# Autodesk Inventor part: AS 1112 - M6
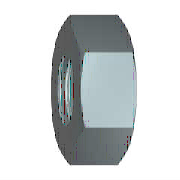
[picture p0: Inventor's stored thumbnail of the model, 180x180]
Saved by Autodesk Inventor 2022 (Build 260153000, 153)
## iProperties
Created: 2021-02
Part Number: AS 1112 - M6
Material: Acciaio, Dolce
Description: Dadi esagonali metrici ISO, inclusi dadi sottili, dadi con intaglio e dadi a corona
Document SubType Name: Modeling
Standard: AS 1112
Designer: admin
Standards Organization: AS
Language: it-IT
Size Designation: M6
Categories: <MemberInstance><Categories><Category DisplayName="Elementi di fissaggio" InternalName="e4da775c-781d-43d5-af7c-5136215cf5a6" Mnemonic="FSTN"><Category DisplayN
Density: 7.85 g/cm^3
Appearance: Semilucidato
IsCustomPart: 0
Author: admin
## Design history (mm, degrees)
sketch "Schizzo1"
  geometry: L1 (-5.774, 0)-(-2.887, 5); L2 (-2.887, 5)-(2.887, 5); L3 (2.887, 5)-(5.774, 0); L4 (5.774, 0)-(2.887, -5); L5 (2.887, -5)-(-2.887, -5); L6 (-2.887, -5)-(-5.774, 0); 2 further points
  constraints: 12 end point, 1 coincident, 1 horizontal, 11 other
  dimensions: "d0" = 11.54701 distance of L3.end L1.start (= 1.1547 x SW)
extrude "Corpo" new body sketch "Schizzo1" distance "d1" = 3.6 (= KOH); taper "d2" = 0 deg
sketch "Schizzo2"
  geometry: L1 (0, 2.887)-(0, 5.774) reference; L2 (0, 5.774)-(3.6, 5.774) reference; L3 (3.6, 2.887)-(3.6, 5.774) reference; L4 (-0.72, 0)-(4.32, 0) reference; L5 (0.447, 5.774)-(0, 5); L6 (3.153, 5.774)-(3.6, 5)
  constraints: 4 end point, 4 point on line
  dimensions: "d3" = 30 deg angle of L1 L5 (= ANG1); "d4" = 30 deg angle of L3 L6 (= ANG2); "d5" = 10 diameter of L5.end L4 (= SW0); "d6" = 10 diameter of L6.end L4 (= SW01)
revolve "Smusso1" sketch "Schizzo2" stored, may be unused: angle "d7" = 90 deg
sketch "Schizzo3"
  geometry: A1 r 5 centre (0, 0) between (-2.5, -4.33) and (2.5, -4.33) reference; 1 further point
  constraints: 1 coincident
hole "Filettatura" sketch "Schizzo3" at (0, 0) diameter "d25" = 4.917; stored, may be unused: countersink angle "d29" = 82 deg, drill point angle "d31" = 118 deg; dims "d26" = 6, "d27" = 4, "d28" = 2, "d30" = 8
workaxis "Work Axis1"
workplane "Work Plane1"
body "Solid1"
chamfer "Smusso2" distance "d8" = 0.54127 (= -0.5 x GD1 + 0.5 x NND); stored, may be unused: angle "d9" = 30 deg, second distance "d40" = 0.54127 (= -0.5 x GD1 + 0.5 x NND)
chamfer "Smusso3" distance "d10" = 0.54127 (= -0.5 x GD1 + 0.5 x NND); stored, may be unused: angle "d11" = 30 deg, second distance "d41" = 0.54127 (= -0.5 x GD1 + 0.5 x NND)
other parameters: "ANG1" = 30 deg [user parameter; used in 1 equation term], "ANG2" = 30 deg [user parameter; used in 1 equation term], "NND" = 6 [user parameter; used in 4 equation terms], "KOH" = 3.6 [user parameter; used in 1 equation term], "SW0" = 10 (= SW) [user parameter; used in 1 equation term], "SW01" = 10 (= SW) [user parameter; used in 1 equation term], "GD1" = 4.91747 (computed from THREADDIA, PTC, TOA) [user parameter; used in 4 equation terms], "d13" = 0, "d14" = 0, "d39" = 0, "d42" = 0, "GUL" = 0.54127 (= 0.541266 x PTC) [user parameter], "THREADDIA" = 6 [user parameter; used in 1 equation term], "TOA" = 30 deg [user parameter; used in 1 equation term], "PTC" = 1 [user parameter; used in 4 equation terms], "E0" = 11.55 (= 1.155 x SW) [user parameter], "GAL" = 0.54127 (= 0.541266 x PTC) [user parameter]
